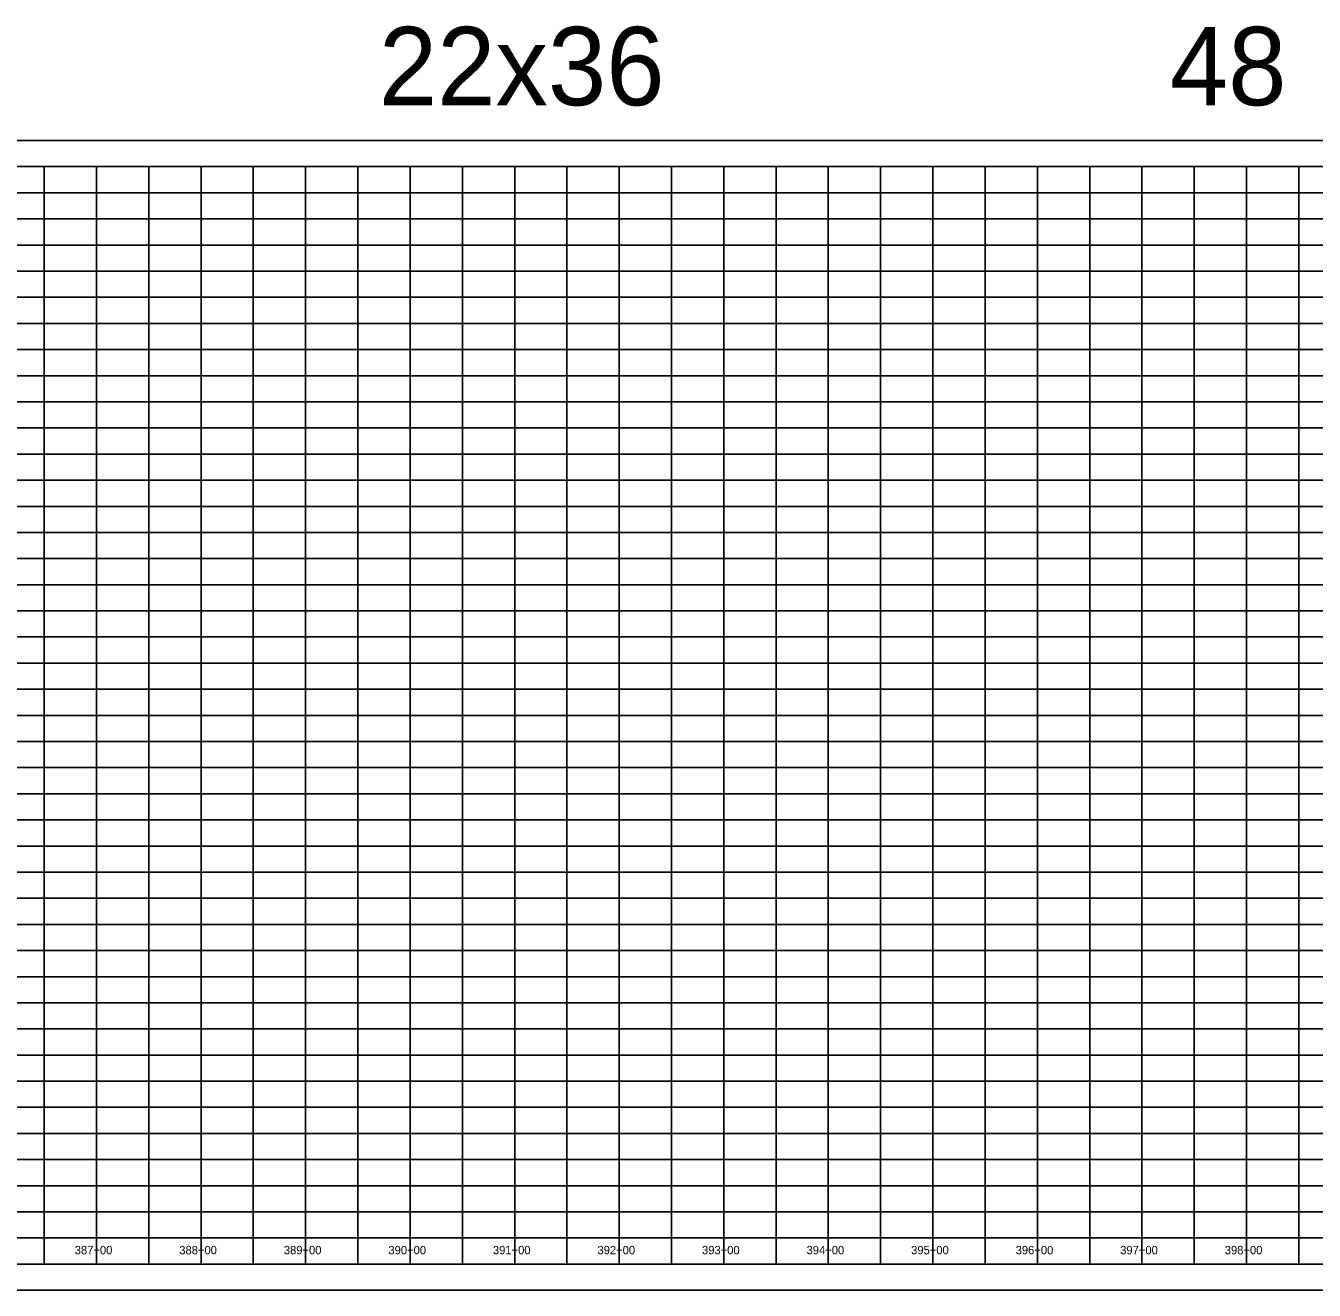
# Model space of a CAD drawing. Extents: x 1873632 to 1926512, y 813126 to 836257.
# Drawn here: x 1916995 to 1918228, y 827963 to 829173 of the extents above; entities that cross this region are included whole.
import ezdxf

# ---------------------------------------------------------------- set-up
doc = ezdxf.new("R2010")
doc.units = 0
for name, color, linetype in [('RD_DDB_StaTX', 7, 'Continuous'), ('RD_PD_WallFill', 7, 'Continuous'), ('RD_SHT_IplotShp', 7, 'Continuous')]:
    doc.layers.add(name, color=color, linetype=linetype)

msp = doc.modelspace()

# ---------------------------------------------------------------- linework, layer by layer
at = {"layer": 'RD_PD_WallFill'}
for p, q in [((1915763, 829038.1), (1921113, 829038.1)), ((1915763, 829038.1), (1917513, 829038.1)), ((1917013, 827988.1), (1917013, 829038.1)), ((1917013, 827988.1), (1917013, 829038.1)), ((1917063, 827988.1), (1917063, 829038.1)), ((1917063, 827988.1), (1917063, 829038.1)), ((1917113, 827988.1), (1917113, 829038.1)), ((1917113, 827988.1), (1917113, 829038.1)), ((1917163, 827988.1), (1917163, 829038.1)), ((1917163, 827988.1), (1917163, 829038.1)), ((1917213, 827988.1), (1917213, 829038.1)), ((1917213, 827988.1), (1917213, 829038.1)), ((1917263, 827988.1), (1917263, 829038.1)), ((1917263, 827988.1), (1917263, 829038.1)), ((1917313, 827988.1), (1917313, 829038.1)), ((1917313, 827988.1), (1917313, 829038.1)), ((1917363, 827988.1), (1917363, 829038.1)), ((1917363, 827988.1), (1917363, 829038.1)), ((1917413, 827988.1), (1917413, 829038.1)), ((1917413, 827988.1), (1917413, 829038.1)), ((1917463, 827988.1), (1917463, 829038.1)), ((1917463, 827988.1), (1917463, 829038.1)), ((1917513, 827988.1), (1917513, 829038.1)), ((1917513, 827988.1), (1917513, 829038.1)), ((1917563, 827988.1), (1917563, 829038.1)), ((1917563, 827988.1), (1917563, 829038.1)), ((1917613, 827988.1), (1917613, 829038.1)), ((1917613, 827988.1), (1917613, 829038.1)), ((1917663, 827988.1), (1917663, 829038.1)), ((1917663, 827988.1), (1917663, 829038.1)), ((1917713, 827988.1), (1917713, 829038.1)), ((1917713, 827988.1), (1917713, 829038.1)), ((1917763, 827988.1), (1917763, 829038.1)), ((1917763, 827988.1), (1917763, 829038.1)), ((1917813, 827988.1), (1917813, 829038.1)), ((1917813, 827988.1), (1917813, 829038.1)), ((1917863, 827988.1), (1917863, 829038.1)), ((1917863, 827988.1), (1917863, 829038.1)), ((1917913, 827988.1), (1917913, 829038.1)), ((1917913, 827988.1), (1917913, 829038.1)), ((1917963, 827988.1), (1917963, 829038.1)), ((1917963, 827988.1), (1917963, 829038.1)), ((1918013, 827988.1), (1918013, 829038.1)), ((1918013, 827988.1), (1918013, 829038.1)), ((1918063, 827988.1), (1918063, 829038.1)), ((1918063, 827988.1), (1918063, 829038.1)), ((1918113, 827988.1), (1918113, 829038.1)), ((1918113, 827988.1), (1918113, 829038.1)), ((1918163, 827988.1), (1918163, 829038.1)), ((1918163, 827988.1), (1918163, 829038.1)), ((1918213, 827988.1), (1918213, 829038.1)), ((1918213, 827988.1), (1918213, 829038.1)), ((1916213, 829013.1), (1921113, 829013.1)), ((1916213, 829013.1), (1921113, 829013.1)), ((1916213, 828988.1), (1921113, 828988.1)), ((1916213, 828963.1), (1921113, 828963.1)), ((1916213, 828938.1), (1921113, 828938.1)), ((1916213, 828913.1), (1921113, 828913.1)), ((1915763, 828888.1), (1921113, 828888.1)), ((1915763, 828863.1), (1921113, 828863.1)), ((1915763, 828838.1), (1921113, 828838.1)), ((1915763, 828813.1), (1921113, 828813.1)), ((1915763, 828788.1), (1921113, 828788.1)), ((1915763, 828763.1), (1921113, 828763.1)), ((1915763, 828738.1), (1921113, 828738.1)), ((1915763, 828713.1), (1921113, 828713.1)), ((1915763, 828688.1), (1921113, 828688.1)), ((1915763, 828663.1), (1921113, 828663.1)), ((1915763, 828638.1), (1921113, 828638.1)), ((1915763, 828613.1), (1921113, 828613.1)), ((1915763, 828588.1), (1921113, 828588.1)), ((1915763, 828563.1), (1921113, 828563.1)), ((1915763, 828538.1), (1921113, 828538.1)), ((1915763, 828513.1), (1921113, 828513.1)), ((1915763, 828488.1), (1921113, 828488.1)), ((1915763, 828463.1), (1921113, 828463.1)), ((1915763, 828438.1), (1921113, 828438.1)), ((1915763, 828413.1), (1921113, 828413.1)), ((1915763, 828388.1), (1921113, 828388.1)), ((1915763, 828363.1), (1921113, 828363.1)), ((1915763, 828338.1), (1921113, 828338.1)), ((1915763, 828313.1), (1921113, 828313.1)), ((1915763, 828288.1), (1921113, 828288.1)), ((1915763, 828263.1), (1921113, 828263.1)), ((1915763, 828238.1), (1921113, 828238.1)), ((1915763, 828213.1), (1921113, 828213.1)), ((1915763, 828188.1), (1921113, 828188.1)), ((1915763, 828163.1), (1921113, 828163.1)), ((1915763, 828138.1), (1921113, 828138.1)), ((1915763, 828113.1), (1921113, 828113.1)), ((1915763, 828088.1), (1921113, 828088.1)), ((1915763, 828063.1), (1921113, 828063.1)), ((1915763, 828038.1), (1921113, 828038.1)), ((1915763, 828013.1), (1921113, 828013.1)), ((1915763, 827988.1), (1921113, 827988.1)), ((1915763, 827988.1), (1921113, 827988.1))]:
    msp.add_line(p, q, dxfattribs=at)
at = {"layer": 'RD_SHT_IplotShp'}
msp.add_lwpolyline([(1915738, 827963.1), (1921138, 827963.1), (1921138, 829063.1), (1915738, 829063.1)], close=True, dxfattribs=at)

# ---------------------------------------------------------------- texts
at = {"layer": 'RD_DDB_StaTX'}
for s, p in [('387+00', (1917042.2, 827997.5)), ('388+00', (1917142.2, 827997.5)), ('389+00', (1917242.2, 827997.5)), ('390+00', (1917342.2, 827997.5)), ('391+00', (1917442.2, 827997.5)), ('392+00', (1917542.2, 827997.5)), ('393+00', (1917642.2, 827997.5)), ('394+00', (1917742.2, 827997.5)), ('395+00', (1917842.2, 827997.5)), ('396+00', (1917942.2, 827997.5)), ('397+00', (1918042.2, 827997.5)), ('398+00', (1918142.2, 827997.5))]:
    msp.add_text(s, height=8, dxfattribs=at).set_placement(p)
at = {"layer": 'RD_PD_WallFill'}
for s, p in [('22x36', (1917333.1, 829096.8)), ('22x36', (1917333.1, 829096.8)), ('22x36', (1917333.1, 829096.8)), ('48', (1918089.7, 829096.8)), ('48', (1918089.7, 829096.8)), ('48', (1918089.7, 829096.8))]:
    msp.add_text(s, height=75, dxfattribs=at).set_placement(p)

doc.saveas('drawing.dxf')
